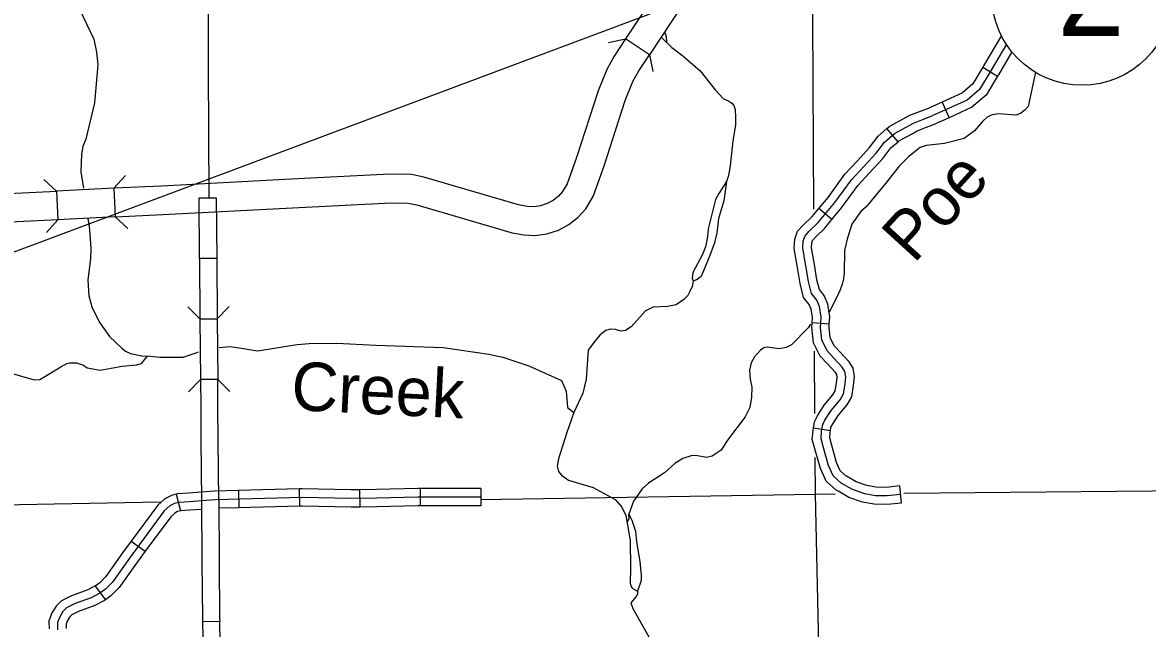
# Model space of a CAD drawing. Extents: x 1373862 to 1376999, y 1168398 to 1170455.
# Drawn here: x 1375214.1 to 1375410.3, y 1168981.2 to 1169087 of the extents above; entities that cross this region are included whole.
import ezdxf

# ---------------------------------------------------------------- set-up
doc = ezdxf.new("R2010")
doc.units = 0
for name, color, linetype in [('21', 7, 'Continuous'), ('Level 10', 7, 'Continuous'), ('Level 31', 7, 'Continuous'), ('Level 32', 7, 'Continuous'), ('Level 35', 7, 'Continuous'), ('Level 37', 7, 'Continuous'), ('Level 38', 7, 'Continuous'), ('Level 45', 7, 'Continuous'), ('Level 5', 7, 'Continuous'), ('R_Draft', 7, 'Continuous')]:
    doc.layers.add(name, color=color, linetype=linetype)

msp = doc.modelspace()

# ---------------------------------------------------------------- linework, layer by layer
at = {"layer": '21'}
msp.add_circle((1375398.88, 1169091.75), 15.74, dxfattribs=at)
at = {"layer": 'Level 10'}
for p, q in [((1375323.46, 1169081.32), (1375319.29, 1169084.09)), ((1375220.07, 1169057.54), (1375220.31, 1169052.55)), ((1375230.07, 1169058.03), (1375230.31, 1169053.03))]:
    msp.add_line(p, q, dxfattribs=at)
for points in [[(1375324.95, 1169092.61), (1375319.29, 1169084.09)], [(1375329.12, 1169089.84), (1375323.46, 1169081.32)], [(1375319.29, 1169084.09), (1375317.3, 1169081.08), (1375316.06, 1169078.78), (1375314.52, 1169075.06), (1375310.77, 1169063.38), (1375309.13, 1169058.78), (1375308.33, 1169057.46), (1375307.6, 1169056.65), (1375306.67, 1169055.92), (1375305.63, 1169055.35), (1375304.44, 1169054.96), (1375303.35, 1169054.81), (1375302.13, 1169054.88), (1375300.64, 1169055.14), (1375284.1, 1169059.98), (1375281.95, 1169060.41), (1375279.73, 1169060.52), (1375277.05, 1169060.42), (1375260.99, 1169059.64), (1375238.36, 1169058.43), (1375230.07, 1169058.03)], [(1375230.31, 1169053.03), (1375238.61, 1169053.44), (1375261.24, 1169054.65), (1375277.26, 1169055.42), (1375279.7, 1169055.51), (1375281.33, 1169055.43), (1375282.91, 1169055.12), (1375299.5, 1169050.26), (1375301.55, 1169049.9), (1375303.56, 1169049.79), (1375305.57, 1169050.07), (1375307.61, 1169050.74), (1375309.42, 1169051.72), (1375311.04, 1169052.98), (1375312.36, 1169054.47), (1375313.67, 1169056.62), (1375315.51, 1169061.78), (1375319.21, 1169073.34), (1375320.59, 1169076.64), (1375321.59, 1169078.5), (1375323.46, 1169081.32)], [(1375038.77, 1169049.32), (1375041.11, 1169051.12), (1375043.64, 1169052.3), (1375046.66, 1169053.28), (1375066.35, 1169056.05), (1375095.4, 1169060.09), (1375098.48, 1169060.45), (1375100.91, 1169060.42), (1375104.16, 1169060.16), (1375144.08, 1169054.72), (1375148.27, 1169054.27), (1375151.45, 1169054.18), (1375156.97, 1169054.33), (1375172.57, 1169055.14), (1375189.14, 1169056.04), (1375220.07, 1169057.54)], [(1375230.07, 1169058.03), (1375220.07, 1169057.54)], [(1375220.31, 1169052.55), (1375189.39, 1169051.04), (1375172.83, 1169050.14), (1375157.17, 1169049.33), (1375151.45, 1169049.18), (1375147.93, 1169049.27), (1375143.48, 1169049.75), (1375103.63, 1169055.19), (1375100.67, 1169055.42), (1375098.74, 1169055.45), (1375096.04, 1169055.13), (1375067.04, 1169051.1), (1375047.79, 1169048.39), (1375045.48, 1169047.64), (1375043.72, 1169046.82), (1375042.03, 1169045.52), (1375039.95, 1169043.53), (1375028.78, 1169031.39)], [(1375230.31, 1169053.03), (1375220.31, 1169052.55)]]:
    msp.add_lwpolyline(points, dxfattribs=at)
at = {"layer": 'Level 31'}
for p, q in [((1375244.92, 1169056.34), (1375247.92, 1169056.37)), ((1375248.01, 1169045.81), (1375245.01, 1169045.79)), ((1375245.09, 1169035.23), (1375248.09, 1169035.25)), ((1375248.18, 1169024.69), (1375245.18, 1169024.67)), ((1375248.53, 1168982.47), (1375245.53, 1168982.41))]:
    msp.add_line(p, q, dxfattribs=at)
for points in [[(1375245.01, 1169045.79), (1375244.92, 1169056.34)], [(1375247.92, 1169056.37), (1375248.01, 1169045.81)], [(1375245.01, 1169045.79), (1375245.09, 1169035.23)], [(1375248.01, 1169045.81), (1375248.09, 1169035.25)], [(1375245.09, 1169035.23), (1375245.18, 1169024.67)], [(1375248.09, 1169035.25), (1375248.18, 1169024.69)], [(1375245.18, 1169024.67), (1375245.22, 1169019.91), (1375245.26, 1169014.11)], [(1375248.26, 1169014.13), (1375248.22, 1169019.93), (1375248.18, 1169024.69)], [(1375245.26, 1169014.11), (1375245.35, 1169003.55)], [(1375248.35, 1169003.57), (1375248.26, 1169014.13)], [(1375245.35, 1169003.55), (1375245.44, 1168992.99)], [(1375248.35, 1169003.57), (1375248.44, 1168993.01)], [(1375245.44, 1168992.99), (1375245.52, 1168982.91), (1375245.53, 1168982.41)], [(1375248.44, 1168993.01), (1375248.52, 1168982.96), (1375248.53, 1168982.47)], [(1375245.53, 1168982.41), (1375245.75, 1168971.85)], [(1375248.75, 1168971.91), (1375248.53, 1168982.47)]]:
    msp.add_lwpolyline(points, dxfattribs=at)
at = {"layer": 'Level 32'}
for p, q in [((1375381.59, 1169079.14), (1375384.16, 1169077.59)), ((1375374.49, 1169073.08), (1375375.74, 1169070.35)), ((1375366.82, 1169066.16), (1375364.87, 1169068.44)), ((1375240.92, 1169004.66), (1375241.68, 1169001.76)), ((1375251.8, 1169005.29), (1375251.88, 1169002.29)), ((1375262.36, 1169005.58), (1375262.44, 1169002.58)), ((1375272.93, 1169005.42), (1375272.98, 1169002.42)), ((1375283.51, 1169005.63), (1375283.51, 1169002.63)), ((1375294.07, 1169005.63), (1375294.07, 1169002.63)), ((1375233.1, 1168996.48), (1375235.51, 1168994.7)), ((1375226.81, 1168988.64), (1375228.59, 1168986.22))]:
    msp.add_line(p, q, dxfattribs=at)
for points in [[(1375384.84, 1169084.68), (1375381.73, 1169079.38), (1375381.59, 1169079.14)], [(1375385.7, 1169083.18), (1375383.02, 1169078.61), (1375381.01, 1169075.27), (1375378.89, 1169073.43), (1375372.88, 1169070.7)], [(1375386.67, 1169081.86), (1375384.31, 1169077.84), (1375384.16, 1169077.59)], [(1375381.59, 1169079.14), (1375379.84, 1169076.24), (1375378.07, 1169074.71), (1375374.49, 1169073.08)], [(1375384.16, 1169077.59), (1375382.17, 1169074.29), (1375379.7, 1169072.16), (1375375.74, 1169070.35)], [(1375374.49, 1169073.08), (1375372.31, 1169072.09)], [(1375367.71, 1169070.14), (1375368.88, 1169070.77), (1375370.7, 1169071.49), (1375372.31, 1169072.09)], [(1375364.87, 1169068.44), (1375365.35, 1169068.85), (1375367.71, 1169070.14)], [(1375369.15, 1169067.5), (1375370.15, 1169068.05), (1375371.78, 1169068.69), (1375373.46, 1169069.31)], [(1375375.74, 1169070.35), (1375373.46, 1169069.31)], [(1375366.82, 1169066.16), (1375367.07, 1169066.37), (1375369.15, 1169067.5)], [(1375294.07, 1169004.13), (1375283.08, 1169004.13), (1375275.91, 1169003.97), (1375271.43, 1169003.9), (1375262.92, 1169004.09), (1375247.73, 1169003.68), (1375243.21, 1169003.36), (1375241.39, 1169003.23), (1375240.65, 1169003.04), (1375239.82, 1169002.62), (1375238.86, 1169001.76), (1375232.78, 1168993.53), (1375229.84, 1168989.34), (1375228.59, 1168988.08), (1375227.63, 1168987.38), (1375226.13, 1168986.61), (1375223.31, 1168985.59), (1375221.84, 1168984.82), (1375221.17, 1168984.18), (1375220.63, 1168983.28), (1375220.24, 1168982.26), (1375220.27, 1168980.98)], [(1375240.92, 1169004.66), (1375240.12, 1169004.45), (1375238.97, 1169003.87), (1375237.75, 1169002.77), (1375233.1, 1168996.48)], [(1375251.8, 1169005.29), (1375247.65, 1169005.18), (1375243.11, 1169004.85), (1375241.15, 1169004.72), (1375240.92, 1169004.66)], [(1375262.36, 1169005.58), (1375251.8, 1169005.29)], [(1375272.93, 1169005.42), (1375271.44, 1169005.4), (1375262.92, 1169005.6), (1375262.36, 1169005.58)], [(1375283.51, 1169005.63), (1375283.06, 1169005.63), (1375275.89, 1169005.47), (1375272.93, 1169005.42)], [(1375294.07, 1169005.63), (1375283.51, 1169005.63)], [(1375245.28, 1169002), (1375243.32, 1169001.86), (1375241.63, 1169001.74), (1375241.68, 1169001.76)], [(1375251.88, 1169002.29), (1375248.4, 1169002.2)], [(1375262.44, 1169002.58), (1375251.88, 1169002.29)], [(1375272.98, 1169002.42), (1375271.43, 1169002.4), (1375262.93, 1169002.59), (1375262.44, 1169002.58)], [(1375283.51, 1169002.63), (1375283.1, 1169002.63), (1375275.94, 1169002.47), (1375272.98, 1169002.42)], [(1375294.07, 1169002.63), (1375283.51, 1169002.63)], [(1375241.68, 1169001.76), (1375241.19, 1169001.63), (1375240.68, 1169001.37), (1375239.98, 1169000.74), (1375235.51, 1168994.7)], [(1375233.1, 1168996.48), (1375231.57, 1168994.41), (1375228.69, 1168990.3), (1375227.61, 1168989.22), (1375226.81, 1168988.64)], [(1375235.51, 1168994.7), (1375234, 1168992.65), (1375230.99, 1168988.37), (1375229.57, 1168986.94), (1375228.59, 1168986.22)], [(1375226.84, 1168988.66), (1375225.53, 1168987.99), (1375222.71, 1168986.96), (1375220.96, 1168986.05), (1375219.99, 1168985.13), (1375219.27, 1168983.94), (1375218.73, 1168982.51), (1375218.77, 1168981.16)], [(1375228.59, 1168986.22), (1375228.42, 1168986.1), (1375226.73, 1168985.23), (1375223.92, 1168984.21), (1375222.72, 1168983.59), (1375222.35, 1168983.23), (1375221.98, 1168982.62), (1375221.75, 1168982), (1375221.77, 1168981.23)]]:
    msp.add_lwpolyline(points, dxfattribs=at)
at = {"layer": 'Level 35'}
for points in [[(1375211.27, 1169105.7), (1375214.35, 1169101.36), (1375215.61, 1169099.94), (1375218.74, 1169096.94), (1375221.57, 1169093.51), (1375222.43, 1169092.2), (1375224.13, 1169089.14), (1375226.59, 1169084.05), (1375227.03, 1169081.75), (1375227.3, 1169079.57), (1375226.7, 1169072.93), (1375225.16, 1169066.59), (1375224.66, 1169065.34), (1375224.42, 1169064.01), (1375224.34, 1169060.89), (1375224.76, 1169058.05)], [(1375326.14, 1169085.21), (1375326.37, 1169084.51), (1375326.41, 1169083.53)], [(1375325.61, 1169084.28), (1375325.66, 1169084.2), (1375327.36, 1169082.62), (1375329.26, 1169081.15), (1375332.32, 1169078.53), (1375334.93, 1169075.18), (1375336.31, 1169073.68), (1375337.32, 1169073.22), (1375337.83, 1169072.88), (1375338.19, 1169072.49), (1375338.38, 1169071.79), (1375338.48, 1169070.39)], [(1375390.79, 1169078.26), (1375389.47, 1169072.29), (1375388.99, 1169071.7), (1375388.14, 1169071.07), (1375387.33, 1169070.76), (1375384.37, 1169071.01), (1375383.23, 1169070.83), (1375382.42, 1169070.52), (1375381.53, 1169069.71), (1375380.15, 1169068.08), (1375378.34, 1169066.69), (1375374.93, 1169065.86), (1375371.74, 1169065.49), (1375370.64, 1169065.15), (1375368.71, 1169063.58), (1375367.02, 1169061.87), (1375364.62, 1169058.84), (1375361.23, 1169054.78), (1375360.32, 1169053.97), (1375358.75, 1169051.76), (1375357.91, 1169049.16), (1375357.5, 1169047.17), (1375357.42, 1169043.24), (1375357.3, 1169042.26), (1375357.05, 1169041.33), (1375356.71, 1169040.3), (1375356.13, 1169039.03), (1375354.8, 1169036.43)], [(1375338.48, 1169070.39), (1375338.44, 1169069.04), (1375338.01, 1169066.29), (1375337.53, 1169061.94), (1375337.26, 1169060.27), (1375336.91, 1169059.2), (1375335.57, 1169057.12), (1375335, 1169056.06), (1375333.7, 1169050.93), (1375333.56, 1169049.57), (1375333.23, 1169047.8), (1375332.73, 1169046.49), (1375331.04, 1169043.34), (1375330.93, 1169042.33), (1375331.1, 1169041.81), (1375330.9, 1169040.89), (1375330.51, 1169040), (1375330.16, 1169039.33), (1375329.43, 1169038.64), (1375328.13, 1169037.72), (1375326.59, 1169037.4), (1375324.13, 1169037.28), (1375322.8, 1169036.68), (1375320.29, 1169033.85), (1375319.3, 1169033.2), (1375318.46, 1169033.1), (1375317.54, 1169033.39), (1375316.64, 1169033.44), (1375315.86, 1169033.2), (1375314.85, 1169032.45), (1375313.95, 1169031.37), (1375312.77, 1169029.79), (1375312.43, 1169024.71), (1375311.83, 1169022.3), (1375310.3, 1169018.89), (1375309.07, 1169015.42), (1375307.61, 1169010.81), (1375307.38, 1169009.58), (1375307.62, 1169008.65), (1375308.11, 1169008.01), (1375309.34, 1169007.11), (1375313.66, 1169005.81), (1375317.51, 1169003.75), (1375318.67, 1169002.42), (1375319.37, 1169000.97), (1375320.08, 1168996.57), (1375320.17, 1168991.78), (1375320.11, 1168989.17), (1375320.22, 1168988.69), (1375320.4, 1168988.38), (1375320.62, 1168988.16), (1375321.39, 1168987.77), (1375321.4, 1168987.21), (1375321.16, 1168986.81), (1375320.22, 1168985.71), (1375320.54, 1168984.73), (1375324.17, 1168978.31)], [(1375336.91, 1169059.2), (1375336.45, 1169055.83), (1375335.53, 1169052.75), (1375335.19, 1169050.27), (1375334.78, 1169048.5), (1375334.01, 1169046.33), (1375332.49, 1169042.62), (1375331.8, 1169042.11), (1375331.1, 1169041.85)], [(1375225.55, 1169052.71), (1375225.75, 1169051.41), (1375225.94, 1169049.29), (1375226.05, 1169047.5), (1375226.01, 1169045.76), (1375225.51, 1169041.98), (1375225.71, 1169039.28), (1375226.28, 1169037.15), (1375227.62, 1169034.58), (1375229.32, 1169032.2), (1375231.45, 1169030.13), (1375232.12, 1169029.62), (1375232.96, 1169029.19), (1375234.95, 1169028.82), (1375236.45, 1169028.76), (1375238.08, 1169028.55), (1375240.27, 1169028.59), (1375242.17, 1169028.59), (1375244.27, 1169029.28), (1375244.86, 1169029.48)], [(1375351.54, 1169034.3), (1375351.16, 1169033.7), (1375348.22, 1169030.73), (1375347.29, 1169030.24), (1375346.07, 1169030.04), (1375343.97, 1169030.29), (1375343.41, 1169030.2), (1375342.8, 1169029.81), (1375341.78, 1169028.65), (1375341.17, 1169027.58), (1375340.91, 1169026.29)], [(1375248.44, 1169030.23), (1375250.37, 1169030.42), (1375252.69, 1169030.08), (1375255.12, 1169029.65), (1375262.06, 1169030.8), (1375264.1, 1169030.93)], [(1375264.1, 1169030.93), (1375268.96, 1169031.02), (1375275.74, 1169030.67), (1375287.48, 1169030.26), (1375295.43, 1169029.1), (1375297.92, 1169028.56), (1375302.44, 1169027.05), (1375308.14, 1169024.47), (1375308.96, 1169022.66), (1375309.15, 1169019.79), (1375310.3, 1169018.89)], [(1375210.96, 1169026.15), (1375216.2, 1169024.61), (1375217.18, 1169024.68), (1375220.82, 1169026.86), (1375221.85, 1169027.44), (1375222.35, 1169027.59), (1375223.57, 1169027.58), (1375224.76, 1169027.18), (1375225.4, 1169026.69), (1375227.71, 1169026.3), (1375231.54, 1169027), (1375234.01, 1169027.24), (1375234.91, 1169027.48), (1375235.91, 1169028.77)], [(1375340.91, 1169026.29), (1375341.02, 1169024.71), (1375341.3, 1169023.35), (1375341.28, 1169021.59), (1375340.99, 1169019.8), (1375340.18, 1169018.18), (1375337.06, 1169014.07), (1375335.95, 1169012.33), (1375334.4, 1169011.3), (1375333.41, 1169011.04), (1375331.84, 1169011.38), (1375330.94, 1169011.41), (1375329.27, 1169010.9), (1375327.91, 1169010.02), (1375326.07, 1169008.39), (1375323.3, 1169006.58), (1375322.18, 1169005.58), (1375320.71, 1169003.47), (1375319.89, 1169001.18)], [(1375319.57, 1168999.81), (1375319.9, 1169000.37), (1375319.89, 1169001.18), (1375320.4, 1169000.12), (1375321.03, 1168998.23), (1375321.2, 1168996.33), (1375321.79, 1168992.95), (1375322.03, 1168990.55), (1375322.04, 1168989.58), (1375321.39, 1168987.77)]]:
    msp.add_lwpolyline(points, dxfattribs=at)
at = {"layer": 'Level 37'}
for points in [[(1375316.35, 1169083.49), (1375319.29, 1169084.09)], [(1375323.46, 1169081.32), (1375324.05, 1169078.38)], [(1375217.85, 1169059.56), (1375220.07, 1169057.54)], [(1375230.07, 1169058.03), (1375232.08, 1169060.25)], [(1375232.53, 1169051.02), (1375230.31, 1169053.03)], [(1375220.31, 1169052.55), (1375218.3, 1169050.32)]]:
    msp.add_lwpolyline(points, dxfattribs=at)
at = {"layer": 'Level 38'}
for points in [[(1375245.09, 1169035.23), (1375242.95, 1169037.33)], [(1375250.2, 1169037.39), (1375248.09, 1169035.25)], [(1375243.07, 1169022.53), (1375245.18, 1169024.67)], [(1375248.18, 1169024.69), (1375250.32, 1169022.59)]]:
    msp.add_lwpolyline(points, dxfattribs=at)
at = {"layer": 'Level 45'}
for p, q in [((1375355.29, 1169052.58), (1375352.98, 1169054.5)), ((1375354.82, 1169034.34), (1375351.83, 1169034.58)), ((1375355.01, 1169015.7), (1375352.05, 1169016.18)), ((1375367.05, 1169006.1), (1375367.38, 1169003.12))]:
    msp.add_line(p, q, dxfattribs=at)
for points in [[(1375367.22, 1169004.61), (1375364.92, 1169004.36), (1375362.8, 1169004.39), (1375361, 1169004.72), (1375358.88, 1169005.47), (1375356.9, 1169006.59), (1375355.5, 1169007.85), (1375354.67, 1169009.68), (1375353.74, 1169012.99), (1375353.38, 1169014.35), (1375353.49, 1169015.68), (1375353.67, 1169016.8), (1375354.06, 1169017.59), (1375355.14, 1169019.28), (1375356.69, 1169021.11), (1375357.3, 1169022.16), (1375357.59, 1169023.85), (1375357.73, 1169025.14), (1375357.55, 1169026.08), (1375357.08, 1169026.83), (1375355.61, 1169028.42), (1375354.49, 1169029.6), (1375353.52, 1169031.51), (1375353.27, 1169033.77), (1375353.42, 1169035.53), (1375353.13, 1169037.4), (1375352.63, 1169038.52), (1375351.73, 1169039.67), (1375351.19, 1169041.75), (1375350.22, 1169047.58), (1375350.29, 1169048.84), (1375350.61, 1169049.74), (1375351.33, 1169050.53), (1375352.91, 1169052.08), (1375355.79, 1169055.53), (1375358.7, 1169059.52), (1375363.01, 1169064.16), (1375364.45, 1169066.1), (1375366.21, 1169067.61), (1375369.52, 1169069.41), (1375371.24, 1169070.09), (1375372.88, 1169070.7)], [(1375359.67, 1169062.77), (1375361.86, 1169065.12), (1375363.34, 1169067.13), (1375364.87, 1169068.44)], [(1375361.86, 1169060.72), (1375364.17, 1169063.2), (1375365.55, 1169065.07), (1375366.82, 1169066.16)], [(1375352.98, 1169054.5), (1375354.6, 1169056.45), (1375357.54, 1169060.48), (1375359.67, 1169062.77)], [(1375355.29, 1169052.58), (1375356.97, 1169054.61), (1375359.86, 1169058.56), (1375361.86, 1169060.72)], [(1375349.26, 1169044.22), (1375348.71, 1169047.5), (1375348.8, 1169049.14), (1375349.3, 1169050.53), (1375350.25, 1169051.57), (1375351.81, 1169053.1), (1375352.98, 1169054.5)], [(1375352.22, 1169044.72), (1375351.73, 1169047.66), (1375351.77, 1169048.54), (1375351.92, 1169048.95), (1375352.41, 1169049.49), (1375354.02, 1169051.06), (1375355.29, 1169052.58)], [(1375351.83, 1169034.58), (1375351.91, 1169035.48), (1375351.68, 1169036.97), (1375351.33, 1169037.74), (1375350.35, 1169038.99), (1375349.72, 1169041.44), (1375349.26, 1169044.22)], [(1375354.82, 1169034.34), (1375354.93, 1169035.59), (1375354.58, 1169037.83), (1375353.92, 1169039.3), (1375353.1, 1169040.35), (1375352.66, 1169042.07), (1375352.22, 1169044.72)], [(1375356.22, 1169025.03), (1375356.13, 1169025.52), (1375355.88, 1169025.92), (1375354.51, 1169027.39), (1375353.25, 1169028.73), (1375352.06, 1169031.07), (1375351.77, 1169033.75), (1375351.83, 1169034.58)], [(1375359.17, 1169025.6), (1375358.97, 1169026.63), (1375358.28, 1169027.75), (1375356.7, 1169029.44), (1375355.73, 1169030.47), (1375354.99, 1169031.94), (1375354.78, 1169033.79), (1375354.82, 1169034.34)], [(1375355.01, 1169015.7), (1375355.11, 1169016.33), (1375355.37, 1169016.85), (1375356.35, 1169018.39), (1375357.92, 1169020.24), (1375358.73, 1169021.63), (1375359.07, 1169023.64), (1375359.24, 1169025.2), (1375359.17, 1169025.6)], [(1375352.05, 1169016.18), (1375352.22, 1169017.26), (1375352.76, 1169018.33), (1375353.93, 1169020.17), (1375355.46, 1169021.98), (1375355.87, 1169022.68), (1375356.1, 1169024.05), (1375356.21, 1169025.08), (1375356.22, 1169025.03)], [(1375356.36, 1169005.17), (1375356.02, 1169005.36), (1375354.26, 1169006.94), (1375353.26, 1169009.16), (1375352.29, 1169012.59), (1375351.86, 1169014.22), (1375352, 1169015.86), (1375352.05, 1169016.18)], [(1375357.83, 1169007.79), (1375357.78, 1169007.81), (1375356.74, 1169008.75), (1375356.09, 1169010.19), (1375355.19, 1169013.38), (1375354.9, 1169014.49), (1375354.98, 1169015.5), (1375355.01, 1169015.7)], [(1375367.05, 1169006.1), (1375364.85, 1169005.86), (1375362.94, 1169005.89), (1375361.39, 1169006.17), (1375359.5, 1169006.84), (1375357.83, 1169007.79)], [(1375367.38, 1169003.12), (1375364.99, 1169002.86), (1375362.65, 1169002.9), (1375360.61, 1169003.26), (1375358.25, 1169004.1), (1375356.36, 1169005.17)]]:
    msp.add_lwpolyline(points, dxfattribs=at)
at = {"layer": 'Level 5'}
for points in [[(1375246.49, 1169108.8), (1375246.51, 1169078.96), (1375246.66, 1169056.36)], [(1375351.78, 1169109.85), (1375352.08, 1169054.37)], [(1375352.21, 1169029.64), (1375352.27, 1169018.76)], [(1375352.31, 1169011.06), (1375352.35, 1169004.69)], [(1375294.07, 1169003.73), (1375352.35, 1169004.69)], [(1375352.35, 1169004.69), (1375355.83, 1169004.72)], [(1375352.35, 1169004.69), (1375353.36, 1168959.73)], [(1375367.81, 1169004.83), (1375442.1, 1169005.55)], [(1375155.01, 1169001.76), (1375238.15, 1169003.32)]]:
    msp.add_lwpolyline(points, dxfattribs=at)
at = {"layer": 'R_Draft'}
msp.add_line((1375430.86, 1169128.62), (1374608.59, 1168820.86), dxfattribs=at)

# ---------------------------------------------------------------- texts
at = {"layer": '21'}
msp.add_text('2', height=15.85, dxfattribs=at).set_placement((1375394.58, 1169084.57))
at = {"layer": 'Level 35'}
for s, rotation, p in [('Poe', 47.6005, (1375369.56, 1169044.74)), ('Creek', 357.1446, (1375260.87, 1169019.38))]:
    msp.add_text(s, height=8.448, rotation=rotation, dxfattribs=at).set_placement(p)

doc.saveas('drawing.dxf')
